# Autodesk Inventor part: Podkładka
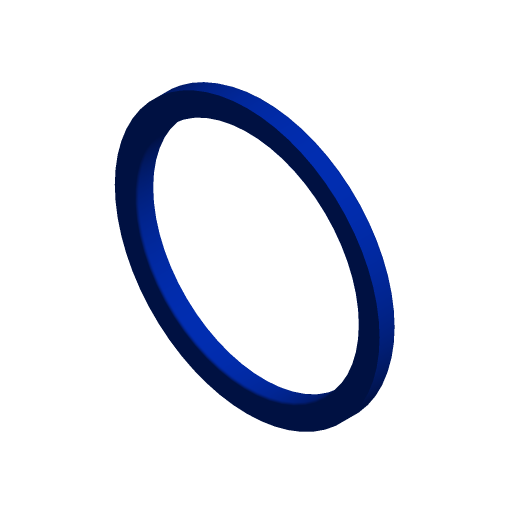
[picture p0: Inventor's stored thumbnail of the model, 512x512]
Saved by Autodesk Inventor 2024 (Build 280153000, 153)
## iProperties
Company: ATC
Shininess: 0.0
Length Units: 11269
Angle Units: 11279
Time Units: 11290
Mass Units: 11283
Length Display Precision: 3
Angle Display Precision: 2
Compacted: True
Created: 2023-03
Part Number: Podkładka
Document SubType Name: Modeling
Designer: Andrzej Jaskulski
Density: 1 g/cm^3
Material: Ogólny
Appearance: Blue(Flat)
Checked By: A.J.
Engr Approved By: Andrzej Jaskulski
Mfg Approved By: Andrzej Jaskulski
Authority: A.J.
Density: 0.0
Volumn: 0.0
Area: 0.0
PropertySet Name: Model Information
Control State: 0
Master: False
Checked Out: False
Title: A.J.: Kurs R2024-MEP
Author: Andrzej Jaskulski
Revision Number: 1/24
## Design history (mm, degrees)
node "Extrusion1" dims "d2" = 2, "d3" = 0
node "Fillet1" dims "d4" = 0.25, "d5" = 0.5
node "Bryła1"
node "Korpusy bryłowe"
node "Korpusy powierzchniowe"
sketch "Sketch1"
  geometry: C1 r 12.5 at (36, 61); C2 r 15 at (36, 61)
  constraints: 2 centre point, 1 coincident
  dimensions: "d0" = 25 diameter of C1; "d1" = 30 diameter of C2
